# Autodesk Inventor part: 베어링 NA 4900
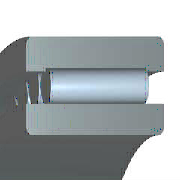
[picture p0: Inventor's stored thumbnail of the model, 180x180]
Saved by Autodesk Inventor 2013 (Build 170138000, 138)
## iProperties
Created: 2009-02
Part Number: 베어링 NA 4900
Material: Steel, Mild
Description: 니들 롤러 베어링 - 경계 치수 및 공차
Document SubType Name: Modeling
Standard: KS B 2029
Designer: KYOUNG IL JANG
Standards Organization: KS
Language: ko-KR
Size Designation: NA 4900 - 10 x 22 x 13
Categories: <MemberInstance><Categories><Category DisplayName="샤프트 부품" InternalName="7f7aeb1f-a693-4053-b835-cee3144e0d98" Mnemonic="SHFT"><Category DisplayName="베어링" Inter
Density: 7.86 g/cm^3
Mass: 23.8214 g
Surface Area: 38.613 cm^2
Volume: 3.03071 cm^3
Company: 한국ATC센터
IsCustomPart: 0
Author: KYOUNG IL JANG
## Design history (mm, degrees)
sketch "스케치"
  geometry: L1 (1.857, 9)-(11.143, 9); L2 (11.143, 9)-(11.143, 7); L3 (13, 7)-(0, 7); L4 (1.857, 7)-(1.857, 9); L5 (1.857, 8)-(11.143, 8); L6 (6.5, 8)-(6.5, 7); L7 (0, 5)-(13, 5); L8 (0, 11)-(13, 11); L9 (13, 5)-(13, 7); L10 (13, 8.8)-(13, 11); L11 (1.857, 8.8)-(0, 8.8); L12 (11.143, 8.8)-(13, 8.8); L13 (-6, 0)-(36, 0) reference; L14 (0, -1.9)-(0, 14.9) reference
  constraints: 24 end point, 8 point on line, 3 midpoint, 3 parallel, 3 perpendicular, 2 symmetric about line, 1 horizontal, 1 other
  dimensions: "d6" = 10 diameter of L7 L13 (= WD); "d7" = 14 diameter of L3 L13 (= KID1); "d8" = 22 diameter of L8 L13 (= BD); "d9" = 16 diameter of L6.start L13 (= 0.5 x WD + 0.5 x BD); "d10" = 17.6 diameter of L12 L13 (= 0.9 x BD + 0.9 x WD - 0.8 x KID1); "d11" = 18 diameter of L1 L13 (= BD + WD - KID1); "d12" = 1.85714 distance between parallel lines of L14 L4 (= 0.142857 x KB); "d13" = 13 distance between parallel lines of L14 L9 (= KB); "d14" = 11.14286 distance between parallel lines of L14 L2 (= 0.857143 x KB)
revolve "본체" stored, may be unused: angle "d17" = 90 deg
revolve "롤러" stored, may be unused: angle "d18" = 90 deg
pattern_circular "IDS_ARRAYROLLER[SIMPL:T]" dims angle "d2" = 360 deg
body "Solid1"
fillet "모깎기1" dims "d0" = 0.3 (= KRS)
other parameters: "WD" = 10 [user parameter; used in 6 equation terms], "BD" = 22 [user parameter; used in 6 equation terms], "KB" = 13 [user parameter; used in 3 equation terms], "KID1" = 14 [user parameter; used in 4 equation terms], "KRS" = 0.3 [user parameter; used in 1 equation term], "d3" = 0, "d4" = 0, "d5" = 0, "d15" = 0, "d16" = 0, "BC0" = 9150000 [user parameter], "WR" = 5 (= 0.5 x WD) [user parameter], "BBA" = 0 [user parameter], "BC" = 8150000 [user parameter], "BR" = 11 (= 0.5 x BD) [user parameter]
